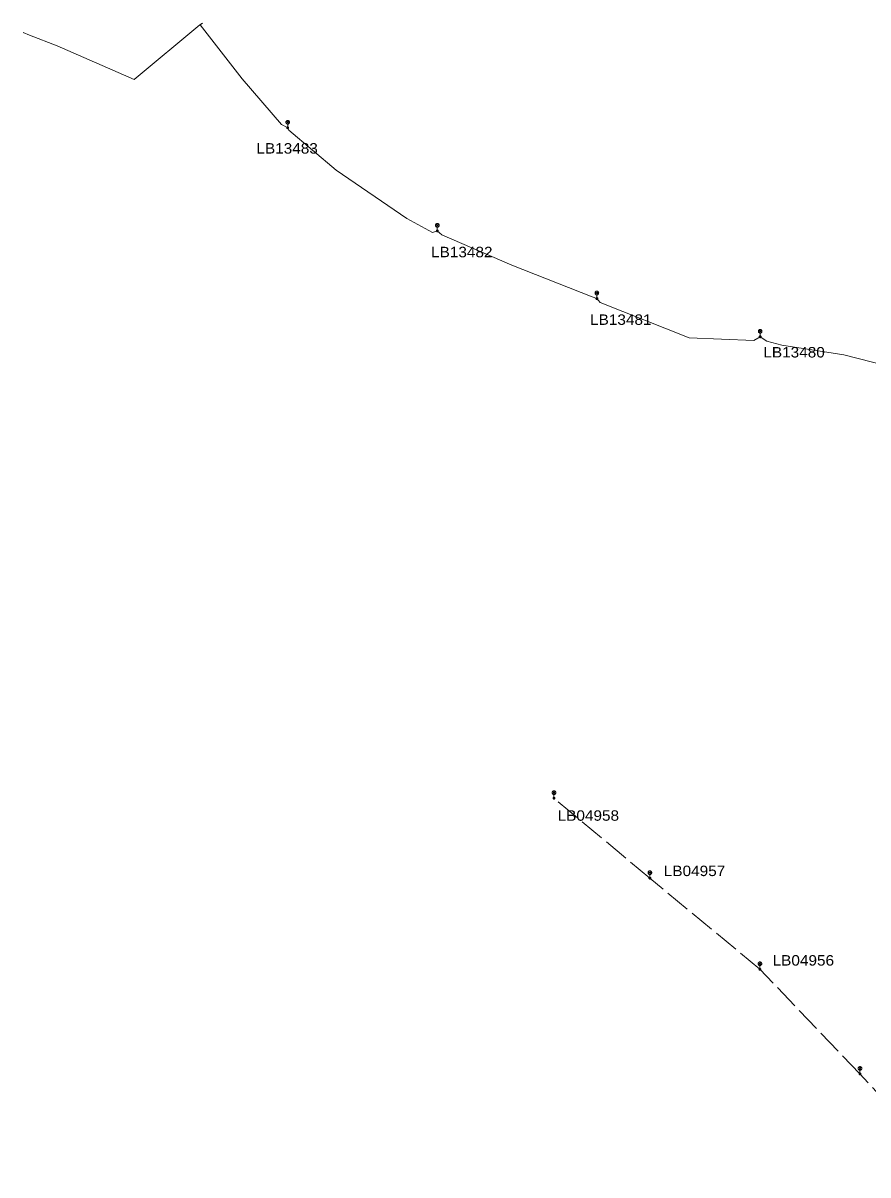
# Model space of a CAD drawing. Extents: x -690018 to -689415, y -972457 to -972107.
# Drawn here: x -690017.9 to -689842.5, y -972367.8 to -972128.6 of the extents above; entities that cross this region are included whole.
import ezdxf

# ---------------------------------------------------------------- set-up
doc = ezdxf.new("R2010")
doc.units = 0
doc.header["$LTSCALE"] = 0.87
doc.linetypes.add('LONG_DASHED', pattern=[7.5, 6, -1.5])
doc.layers.add('1', color=7, linetype='Continuous', lineweight=13)

msp = doc.modelspace()

# ---------------------------------------------------------------- linework, layer by layer
at = {"layer": '1'}
for p, q in [((-689963.195, -972148.955), (-689962.665, -972149.485)), ((-689963.195, -972149.485), (-689962.665, -972148.955)), ((-689962.93, -972150.37), (-689962.93, -972149.595)), ((-689932.135, -972170.365), (-689931.605, -972170.895)), ((-689932.135, -972170.895), (-689931.605, -972170.365)), ((-689931.87, -972171.78), (-689931.87, -972171.005)), ((-689899.005, -972184.415), (-689898.475, -972184.945)), ((-689899.005, -972184.945), (-689898.475, -972184.415)), ((-689898.74, -972185.83), (-689898.74, -972185.055)), ((-689865.095, -972192.355), (-689864.565, -972192.885)), ((-689865.095, -972192.885), (-689864.565, -972192.355)), ((-689864.83, -972193.77), (-689864.83, -972192.995)), ((-689907.912, -972288.185), (-689907.382, -972288.715)), ((-689907.912, -972288.715), (-689907.382, -972288.185)), ((-689907.647, -972289.6), (-689907.647, -972288.825)), ((-689887.998, -972304.793), (-689887.468, -972305.323)), ((-689887.998, -972305.323), (-689887.468, -972304.793)), ((-689887.733, -972306.208), (-689887.733, -972305.433)), ((-689865.155, -972323.71), (-689864.625, -972324.24)), ((-689865.155, -972324.24), (-689864.625, -972323.71)), ((-689864.89, -972325.125), (-689864.89, -972324.35)), ((-689844.376, -972345.444), (-689843.846, -972345.974)), ((-689844.376, -972345.974), (-689843.846, -972345.444)), ((-689844.111, -972346.859), (-689844.111, -972346.084))]:
    msp.add_line(p, q, dxfattribs=at)
at = {"layer": '1', "linetype": 'LONG_DASHED'}
for p, q in [((-689887.733, -972306.208), (-689907.647, -972289.6)), ((-689864.89, -972325.125), (-689887.733, -972306.208)), ((-689844.111, -972346.859), (-689864.89, -972325.125)), ((-689824.64, -972367.84), (-689844.111, -972346.859))]:
    msp.add_line(p, q, dxfattribs=at)
at = {"layer": '1'}
for points in [[(-689980.613, -972128.614), (-689981.155, -972128.982), (-689994.789, -972140.341), (-690010.821, -972133.353), (-690016.558, -972131.106), (-690017.89, -972130.601)], [(-689980.613, -972128.614), (-689981.081, -972129.019), (-689972.397, -972140.21), (-689964.203, -972149.703), (-689962.93, -972150.37)], [(-689962.93, -972150.37), (-689962.694, -972150.846), (-689952.88, -972159.16), (-689938.221, -972169.176), (-689932.88, -972172.102), (-689931.87, -972171.78)], [(-689931.87, -972171.78), (-689930.933, -972172.628), (-689916.423, -972178.917), (-689899.71, -972185.465), (-689898.74, -972185.83)], [(-689864.83, -972193.77), (-689866.149, -972194.545), (-689879.577, -972193.963), (-689898.079, -972186.654), (-689898.74, -972185.83)], [(-689831.69, -972201.27), (-689832.862, -972201.27), (-689847.448, -972197.511), (-689860.303, -972195.527), (-689863.452, -972194.661), (-689864.83, -972193.77)]]:
    msp.add_lwpolyline(points, dxfattribs=at)
for points in [[(-689962.555, -972149.22), (-689962.561, -972149.155), (-689962.578, -972149.092), (-689962.605, -972149.032), (-689962.643, -972148.979), (-689962.689, -972148.933), (-689962.742, -972148.895), (-689962.802, -972148.868), (-689962.865, -972148.851), (-689962.93, -972148.845), (-689962.995, -972148.851), (-689963.058, -972148.868), (-689963.118, -972148.895), (-689963.171, -972148.933), (-689963.217, -972148.979), (-689963.255, -972149.032), (-689963.282, -972149.092), (-689963.299, -972149.155), (-689963.305, -972149.22), (-689963.299, -972149.285), (-689963.282, -972149.348), (-689963.255, -972149.408), (-689963.217, -972149.461), (-689963.171, -972149.507), (-689963.118, -972149.545), (-689963.058, -972149.572), (-689962.995, -972149.589), (-689962.93, -972149.595), (-689962.865, -972149.589), (-689962.802, -972149.572), (-689962.742, -972149.545), (-689962.689, -972149.507), (-689962.643, -972149.461), (-689962.605, -972149.408), (-689962.578, -972149.348), (-689962.561, -972149.285)], [(-689962.74, -972150.37), (-689962.743, -972150.337), (-689962.751, -972150.305), (-689962.765, -972150.275), (-689962.784, -972150.248), (-689962.808, -972150.224), (-689962.835, -972150.205), (-689962.865, -972150.191), (-689962.897, -972150.183), (-689962.93, -972150.18), (-689962.963, -972150.183), (-689962.995, -972150.191), (-689963.025, -972150.205), (-689963.052, -972150.224), (-689963.076, -972150.248), (-689963.095, -972150.275), (-689963.109, -972150.305), (-689963.117, -972150.337), (-689963.12, -972150.37), (-689963.117, -972150.403), (-689963.109, -972150.435), (-689963.095, -972150.465), (-689963.076, -972150.492), (-689963.052, -972150.516), (-689963.025, -972150.535), (-689962.995, -972150.549), (-689962.963, -972150.557), (-689962.93, -972150.56), (-689962.897, -972150.557), (-689962.865, -972150.549), (-689962.835, -972150.535), (-689962.808, -972150.516), (-689962.784, -972150.492), (-689962.765, -972150.465), (-689962.751, -972150.435), (-689962.743, -972150.403)], [(-689962.88, -972150.37), (-689962.881, -972150.361), (-689962.883, -972150.353), (-689962.887, -972150.345), (-689962.892, -972150.338), (-689962.898, -972150.332), (-689962.905, -972150.327), (-689962.913, -972150.323), (-689962.921, -972150.321), (-689962.93, -972150.32), (-689962.939, -972150.321), (-689962.947, -972150.323), (-689962.955, -972150.327), (-689962.962, -972150.332), (-689962.968, -972150.338), (-689962.973, -972150.345), (-689962.977, -972150.353), (-689962.979, -972150.361), (-689962.98, -972150.37), (-689962.979, -972150.379), (-689962.977, -972150.387), (-689962.973, -972150.395), (-689962.968, -972150.402), (-689962.962, -972150.408), (-689962.955, -972150.413), (-689962.947, -972150.417), (-689962.939, -972150.419), (-689962.93, -972150.42), (-689962.921, -972150.419), (-689962.913, -972150.417), (-689962.905, -972150.413), (-689962.898, -972150.408), (-689962.892, -972150.402), (-689962.887, -972150.395), (-689962.883, -972150.387), (-689962.881, -972150.379)], [(-689931.495, -972170.63), (-689931.501, -972170.565), (-689931.518, -972170.502), (-689931.545, -972170.442), (-689931.583, -972170.389), (-689931.629, -972170.343), (-689931.682, -972170.305), (-689931.742, -972170.278), (-689931.805, -972170.261), (-689931.87, -972170.255), (-689931.935, -972170.261), (-689931.998, -972170.278), (-689932.058, -972170.305), (-689932.111, -972170.343), (-689932.157, -972170.389), (-689932.195, -972170.442), (-689932.222, -972170.502), (-689932.239, -972170.565), (-689932.245, -972170.63), (-689932.239, -972170.695), (-689932.222, -972170.758), (-689932.195, -972170.818), (-689932.157, -972170.871), (-689932.111, -972170.917), (-689932.058, -972170.955), (-689931.998, -972170.982), (-689931.935, -972170.999), (-689931.87, -972171.005), (-689931.805, -972170.999), (-689931.742, -972170.982), (-689931.682, -972170.955), (-689931.629, -972170.917), (-689931.583, -972170.871), (-689931.545, -972170.818), (-689931.518, -972170.758), (-689931.501, -972170.695)], [(-689931.68, -972171.78), (-689931.683, -972171.747), (-689931.691, -972171.715), (-689931.705, -972171.685), (-689931.724, -972171.658), (-689931.748, -972171.634), (-689931.775, -972171.615), (-689931.805, -972171.601), (-689931.837, -972171.593), (-689931.87, -972171.59), (-689931.903, -972171.593), (-689931.935, -972171.601), (-689931.965, -972171.615), (-689931.992, -972171.634), (-689932.016, -972171.658), (-689932.035, -972171.685), (-689932.049, -972171.715), (-689932.057, -972171.747), (-689932.06, -972171.78), (-689932.057, -972171.813), (-689932.049, -972171.845), (-689932.035, -972171.875), (-689932.016, -972171.902), (-689931.992, -972171.926), (-689931.965, -972171.945), (-689931.935, -972171.959), (-689931.903, -972171.967), (-689931.87, -972171.97), (-689931.837, -972171.967), (-689931.805, -972171.959), (-689931.775, -972171.945), (-689931.748, -972171.926), (-689931.724, -972171.902), (-689931.705, -972171.875), (-689931.691, -972171.845), (-689931.683, -972171.813)], [(-689931.82, -972171.78), (-689931.821, -972171.771), (-689931.823, -972171.763), (-689931.827, -972171.755), (-689931.832, -972171.748), (-689931.838, -972171.742), (-689931.845, -972171.737), (-689931.853, -972171.733), (-689931.861, -972171.731), (-689931.87, -972171.73), (-689931.879, -972171.731), (-689931.887, -972171.733), (-689931.895, -972171.737), (-689931.902, -972171.742), (-689931.908, -972171.748), (-689931.913, -972171.755), (-689931.917, -972171.763), (-689931.919, -972171.771), (-689931.92, -972171.78), (-689931.919, -972171.789), (-689931.917, -972171.797), (-689931.913, -972171.805), (-689931.908, -972171.812), (-689931.902, -972171.818), (-689931.895, -972171.823), (-689931.887, -972171.827), (-689931.879, -972171.829), (-689931.87, -972171.83), (-689931.861, -972171.829), (-689931.853, -972171.827), (-689931.845, -972171.823), (-689931.838, -972171.818), (-689931.832, -972171.812), (-689931.827, -972171.805), (-689931.823, -972171.797), (-689931.821, -972171.789)], [(-689898.365, -972184.68), (-689898.371, -972184.615), (-689898.388, -972184.552), (-689898.415, -972184.492), (-689898.453, -972184.439), (-689898.499, -972184.393), (-689898.552, -972184.355), (-689898.612, -972184.328), (-689898.675, -972184.311), (-689898.74, -972184.305), (-689898.805, -972184.311), (-689898.868, -972184.328), (-689898.928, -972184.355), (-689898.981, -972184.393), (-689899.027, -972184.439), (-689899.065, -972184.492), (-689899.092, -972184.552), (-689899.109, -972184.615), (-689899.115, -972184.68), (-689899.109, -972184.745), (-689899.092, -972184.808), (-689899.065, -972184.868), (-689899.027, -972184.921), (-689898.981, -972184.967), (-689898.928, -972185.005), (-689898.868, -972185.032), (-689898.805, -972185.049), (-689898.74, -972185.055), (-689898.675, -972185.049), (-689898.612, -972185.032), (-689898.552, -972185.005), (-689898.499, -972184.967), (-689898.453, -972184.921), (-689898.415, -972184.868), (-689898.388, -972184.808), (-689898.371, -972184.745)], [(-689898.55, -972185.83), (-689898.553, -972185.797), (-689898.561, -972185.765), (-689898.575, -972185.735), (-689898.594, -972185.708), (-689898.618, -972185.684), (-689898.645, -972185.665), (-689898.675, -972185.651), (-689898.707, -972185.643), (-689898.74, -972185.64), (-689898.773, -972185.643), (-689898.805, -972185.651), (-689898.835, -972185.665), (-689898.862, -972185.684), (-689898.886, -972185.708), (-689898.905, -972185.735), (-689898.919, -972185.765), (-689898.927, -972185.797), (-689898.93, -972185.83), (-689898.927, -972185.863), (-689898.919, -972185.895), (-689898.905, -972185.925), (-689898.886, -972185.952), (-689898.862, -972185.976), (-689898.835, -972185.995), (-689898.805, -972186.009), (-689898.773, -972186.017), (-689898.74, -972186.02), (-689898.707, -972186.017), (-689898.675, -972186.009), (-689898.645, -972185.995), (-689898.618, -972185.976), (-689898.594, -972185.952), (-689898.575, -972185.925), (-689898.561, -972185.895), (-689898.553, -972185.863)], [(-689898.69, -972185.83), (-689898.691, -972185.821), (-689898.693, -972185.813), (-689898.697, -972185.805), (-689898.702, -972185.798), (-689898.708, -972185.792), (-689898.715, -972185.787), (-689898.723, -972185.783), (-689898.731, -972185.781), (-689898.74, -972185.78), (-689898.749, -972185.781), (-689898.757, -972185.783), (-689898.765, -972185.787), (-689898.772, -972185.792), (-689898.778, -972185.798), (-689898.783, -972185.805), (-689898.787, -972185.813), (-689898.789, -972185.821), (-689898.79, -972185.83), (-689898.789, -972185.839), (-689898.787, -972185.847), (-689898.783, -972185.855), (-689898.778, -972185.862), (-689898.772, -972185.868), (-689898.765, -972185.873), (-689898.757, -972185.877), (-689898.749, -972185.879), (-689898.74, -972185.88), (-689898.731, -972185.879), (-689898.723, -972185.877), (-689898.715, -972185.873), (-689898.708, -972185.868), (-689898.702, -972185.862), (-689898.697, -972185.855), (-689898.693, -972185.847), (-689898.691, -972185.839)], [(-689864.455, -972192.62), (-689864.461, -972192.555), (-689864.478, -972192.492), (-689864.505, -972192.432), (-689864.543, -972192.379), (-689864.589, -972192.333), (-689864.642, -972192.295), (-689864.702, -972192.268), (-689864.765, -972192.251), (-689864.83, -972192.245), (-689864.895, -972192.251), (-689864.958, -972192.268), (-689865.018, -972192.295), (-689865.071, -972192.333), (-689865.117, -972192.379), (-689865.155, -972192.432), (-689865.182, -972192.492), (-689865.199, -972192.555), (-689865.205, -972192.62), (-689865.199, -972192.685), (-689865.182, -972192.748), (-689865.155, -972192.808), (-689865.117, -972192.861), (-689865.071, -972192.907), (-689865.018, -972192.945), (-689864.958, -972192.972), (-689864.895, -972192.989), (-689864.83, -972192.995), (-689864.765, -972192.989), (-689864.702, -972192.972), (-689864.642, -972192.945), (-689864.589, -972192.907), (-689864.543, -972192.861), (-689864.505, -972192.808), (-689864.478, -972192.748), (-689864.461, -972192.685)], [(-689864.64, -972193.77), (-689864.643, -972193.737), (-689864.651, -972193.705), (-689864.665, -972193.675), (-689864.684, -972193.648), (-689864.708, -972193.624), (-689864.735, -972193.605), (-689864.765, -972193.591), (-689864.797, -972193.583), (-689864.83, -972193.58), (-689864.863, -972193.583), (-689864.895, -972193.591), (-689864.925, -972193.605), (-689864.952, -972193.624), (-689864.976, -972193.648), (-689864.995, -972193.675), (-689865.009, -972193.705), (-689865.017, -972193.737), (-689865.02, -972193.77), (-689865.017, -972193.803), (-689865.009, -972193.835), (-689864.995, -972193.865), (-689864.976, -972193.892), (-689864.952, -972193.916), (-689864.925, -972193.935), (-689864.895, -972193.949), (-689864.863, -972193.957), (-689864.83, -972193.96), (-689864.797, -972193.957), (-689864.765, -972193.949), (-689864.735, -972193.935), (-689864.708, -972193.916), (-689864.684, -972193.892), (-689864.665, -972193.865), (-689864.651, -972193.835), (-689864.643, -972193.803)], [(-689864.78, -972193.77), (-689864.781, -972193.761), (-689864.783, -972193.753), (-689864.787, -972193.745), (-689864.792, -972193.738), (-689864.798, -972193.732), (-689864.805, -972193.727), (-689864.813, -972193.723), (-689864.821, -972193.721), (-689864.83, -972193.72), (-689864.839, -972193.721), (-689864.847, -972193.723), (-689864.855, -972193.727), (-689864.862, -972193.732), (-689864.868, -972193.738), (-689864.873, -972193.745), (-689864.877, -972193.753), (-689864.879, -972193.761), (-689864.88, -972193.77), (-689864.879, -972193.779), (-689864.877, -972193.787), (-689864.873, -972193.795), (-689864.868, -972193.802), (-689864.862, -972193.808), (-689864.855, -972193.813), (-689864.847, -972193.817), (-689864.839, -972193.819), (-689864.83, -972193.82), (-689864.821, -972193.819), (-689864.813, -972193.817), (-689864.805, -972193.813), (-689864.798, -972193.808), (-689864.792, -972193.802), (-689864.787, -972193.795), (-689864.783, -972193.787), (-689864.781, -972193.779)], [(-689907.272, -972288.45), (-689907.278, -972288.385), (-689907.295, -972288.321), (-689907.322, -972288.262), (-689907.36, -972288.209), (-689907.406, -972288.162), (-689907.459, -972288.125), (-689907.519, -972288.097), (-689907.582, -972288.08), (-689907.647, -972288.075), (-689907.712, -972288.08), (-689907.775, -972288.097), (-689907.834, -972288.125), (-689907.888, -972288.162), (-689907.934, -972288.209), (-689907.972, -972288.262), (-689907.999, -972288.321), (-689908.016, -972288.385), (-689908.022, -972288.45), (-689908.016, -972288.515), (-689907.999, -972288.578), (-689907.972, -972288.637), (-689907.934, -972288.691), (-689907.888, -972288.737), (-689907.834, -972288.774), (-689907.775, -972288.802), (-689907.712, -972288.819), (-689907.647, -972288.825), (-689907.582, -972288.819), (-689907.519, -972288.802), (-689907.459, -972288.774), (-689907.406, -972288.737), (-689907.36, -972288.691), (-689907.322, -972288.637), (-689907.295, -972288.578), (-689907.278, -972288.515)], [(-689907.457, -972289.6), (-689907.46, -972289.567), (-689907.468, -972289.535), (-689907.482, -972289.505), (-689907.501, -972289.478), (-689907.525, -972289.454), (-689907.552, -972289.435), (-689907.582, -972289.421), (-689907.614, -972289.413), (-689907.647, -972289.41), (-689907.68, -972289.413), (-689907.712, -972289.421), (-689907.742, -972289.435), (-689907.769, -972289.454), (-689907.792, -972289.478), (-689907.811, -972289.505), (-689907.825, -972289.535), (-689907.834, -972289.567), (-689907.837, -972289.6), (-689907.834, -972289.633), (-689907.825, -972289.665), (-689907.811, -972289.695), (-689907.792, -972289.722), (-689907.769, -972289.745), (-689907.742, -972289.764), (-689907.712, -972289.778), (-689907.68, -972289.787), (-689907.647, -972289.79), (-689907.614, -972289.787), (-689907.582, -972289.778), (-689907.552, -972289.764), (-689907.525, -972289.745), (-689907.501, -972289.722), (-689907.482, -972289.695), (-689907.468, -972289.665), (-689907.46, -972289.633)], [(-689907.597, -972289.6), (-689907.598, -972289.591), (-689907.6, -972289.583), (-689907.604, -972289.575), (-689907.609, -972289.568), (-689907.615, -972289.561), (-689907.622, -972289.556), (-689907.63, -972289.553), (-689907.638, -972289.55), (-689907.647, -972289.55), (-689907.656, -972289.55), (-689907.664, -972289.553), (-689907.672, -972289.556), (-689907.679, -972289.561), (-689907.685, -972289.568), (-689907.69, -972289.575), (-689907.694, -972289.583), (-689907.696, -972289.591), (-689907.697, -972289.6), (-689907.696, -972289.608), (-689907.694, -972289.617), (-689907.69, -972289.625), (-689907.685, -972289.632), (-689907.679, -972289.638), (-689907.672, -972289.643), (-689907.664, -972289.647), (-689907.656, -972289.649), (-689907.647, -972289.65), (-689907.638, -972289.649), (-689907.63, -972289.647), (-689907.622, -972289.643), (-689907.615, -972289.638), (-689907.609, -972289.632), (-689907.604, -972289.625), (-689907.6, -972289.617), (-689907.598, -972289.608)], [(-689887.358, -972305.058), (-689887.363, -972304.993), (-689887.38, -972304.93), (-689887.408, -972304.871), (-689887.446, -972304.817), (-689887.492, -972304.771), (-689887.545, -972304.733), (-689887.605, -972304.706), (-689887.668, -972304.689), (-689887.733, -972304.683), (-689887.798, -972304.689), (-689887.861, -972304.706), (-689887.92, -972304.733), (-689887.974, -972304.771), (-689888.02, -972304.817), (-689888.058, -972304.871), (-689888.085, -972304.93), (-689888.102, -972304.993), (-689888.108, -972305.058), (-689888.102, -972305.123), (-689888.085, -972305.186), (-689888.058, -972305.246), (-689888.02, -972305.299), (-689887.974, -972305.345), (-689887.92, -972305.383), (-689887.861, -972305.41), (-689887.798, -972305.427), (-689887.733, -972305.433), (-689887.668, -972305.427), (-689887.605, -972305.41), (-689887.545, -972305.383), (-689887.492, -972305.345), (-689887.446, -972305.299), (-689887.408, -972305.246), (-689887.38, -972305.186), (-689887.363, -972305.123)], [(-689887.543, -972306.208), (-689887.546, -972306.175), (-689887.554, -972306.143), (-689887.568, -972306.113), (-689887.587, -972306.086), (-689887.611, -972306.062), (-689887.638, -972306.044), (-689887.668, -972306.03), (-689887.7, -972306.021), (-689887.733, -972306.018), (-689887.766, -972306.021), (-689887.798, -972306.03), (-689887.828, -972306.044), (-689887.855, -972306.062), (-689887.878, -972306.086), (-689887.897, -972306.113), (-689887.911, -972306.143), (-689887.92, -972306.175), (-689887.923, -972306.208), (-689887.92, -972306.241), (-689887.911, -972306.273), (-689887.897, -972306.303), (-689887.878, -972306.33), (-689887.855, -972306.354), (-689887.828, -972306.373), (-689887.798, -972306.387), (-689887.766, -972306.395), (-689887.733, -972306.398), (-689887.7, -972306.395), (-689887.668, -972306.387), (-689887.638, -972306.373), (-689887.611, -972306.354), (-689887.587, -972306.33), (-689887.568, -972306.303), (-689887.554, -972306.273), (-689887.546, -972306.241)], [(-689887.683, -972306.208), (-689887.684, -972306.199), (-689887.686, -972306.191), (-689887.689, -972306.183), (-689887.694, -972306.176), (-689887.701, -972306.17), (-689887.708, -972306.165), (-689887.716, -972306.161), (-689887.724, -972306.159), (-689887.733, -972306.158), (-689887.741, -972306.159), (-689887.75, -972306.161), (-689887.758, -972306.165), (-689887.765, -972306.17), (-689887.771, -972306.176), (-689887.776, -972306.183), (-689887.78, -972306.191), (-689887.782, -972306.199), (-689887.783, -972306.208), (-689887.782, -972306.217), (-689887.78, -972306.225), (-689887.776, -972306.233), (-689887.771, -972306.24), (-689887.765, -972306.246), (-689887.758, -972306.251), (-689887.75, -972306.255), (-689887.741, -972306.257), (-689887.733, -972306.258), (-689887.724, -972306.257), (-689887.716, -972306.255), (-689887.708, -972306.251), (-689887.701, -972306.246), (-689887.694, -972306.24), (-689887.689, -972306.233), (-689887.686, -972306.225), (-689887.684, -972306.217)], [(-689864.515, -972323.975), (-689864.521, -972323.91), (-689864.538, -972323.847), (-689864.565, -972323.788), (-689864.603, -972323.734), (-689864.649, -972323.688), (-689864.702, -972323.65), (-689864.762, -972323.623), (-689864.825, -972323.606), (-689864.89, -972323.6), (-689864.955, -972323.606), (-689865.018, -972323.623), (-689865.078, -972323.65), (-689865.131, -972323.688), (-689865.177, -972323.734), (-689865.215, -972323.788), (-689865.242, -972323.847), (-689865.259, -972323.91), (-689865.265, -972323.975), (-689865.259, -972324.04), (-689865.242, -972324.103), (-689865.215, -972324.162), (-689865.177, -972324.216), (-689865.131, -972324.262), (-689865.078, -972324.3), (-689865.018, -972324.327), (-689864.955, -972324.344), (-689864.89, -972324.35), (-689864.825, -972324.344), (-689864.762, -972324.327), (-689864.702, -972324.3), (-689864.649, -972324.262), (-689864.603, -972324.216), (-689864.565, -972324.162), (-689864.538, -972324.103), (-689864.521, -972324.04)], [(-689864.7, -972325.125), (-689864.703, -972325.092), (-689864.711, -972325.06), (-689864.725, -972325.03), (-689864.744, -972325.003), (-689864.768, -972324.979), (-689864.795, -972324.96), (-689864.825, -972324.946), (-689864.857, -972324.938), (-689864.89, -972324.935), (-689864.923, -972324.938), (-689864.955, -972324.946), (-689864.985, -972324.96), (-689865.012, -972324.979), (-689865.036, -972325.003), (-689865.055, -972325.03), (-689865.069, -972325.06), (-689865.077, -972325.092), (-689865.08, -972325.125), (-689865.077, -972325.158), (-689865.069, -972325.19), (-689865.055, -972325.22), (-689865.036, -972325.247), (-689865.012, -972325.271), (-689864.985, -972325.29), (-689864.955, -972325.304), (-689864.923, -972325.312), (-689864.89, -972325.315), (-689864.857, -972325.312), (-689864.825, -972325.304), (-689864.795, -972325.29), (-689864.768, -972325.271), (-689864.744, -972325.247), (-689864.725, -972325.22), (-689864.711, -972325.19), (-689864.703, -972325.158)], [(-689864.84, -972325.125), (-689864.841, -972325.116), (-689864.843, -972325.108), (-689864.847, -972325.1), (-689864.852, -972325.093), (-689864.858, -972325.087), (-689864.865, -972325.082), (-689864.873, -972325.078), (-689864.881, -972325.076), (-689864.89, -972325.075), (-689864.899, -972325.076), (-689864.907, -972325.078), (-689864.915, -972325.082), (-689864.922, -972325.087), (-689864.928, -972325.093), (-689864.933, -972325.1), (-689864.937, -972325.108), (-689864.939, -972325.116), (-689864.94, -972325.125), (-689864.939, -972325.134), (-689864.937, -972325.142), (-689864.933, -972325.15), (-689864.928, -972325.157), (-689864.922, -972325.163), (-689864.915, -972325.168), (-689864.907, -972325.172), (-689864.899, -972325.174), (-689864.89, -972325.175), (-689864.881, -972325.174), (-689864.873, -972325.172), (-689864.865, -972325.168), (-689864.858, -972325.163), (-689864.852, -972325.157), (-689864.847, -972325.15), (-689864.843, -972325.142), (-689864.841, -972325.134)], [(-689843.736, -972345.709), (-689843.742, -972345.644), (-689843.759, -972345.581), (-689843.787, -972345.521), (-689843.824, -972345.468), (-689843.87, -972345.422), (-689843.924, -972345.384), (-689843.983, -972345.357), (-689844.046, -972345.34), (-689844.111, -972345.334), (-689844.177, -972345.34), (-689844.24, -972345.357), (-689844.299, -972345.384), (-689844.352, -972345.422), (-689844.399, -972345.468), (-689844.436, -972345.521), (-689844.464, -972345.581), (-689844.481, -972345.644), (-689844.486, -972345.709), (-689844.481, -972345.774), (-689844.464, -972345.837), (-689844.436, -972345.896), (-689844.399, -972345.95), (-689844.352, -972345.996), (-689844.299, -972346.034), (-689844.24, -972346.061), (-689844.177, -972346.078), (-689844.111, -972346.084), (-689844.046, -972346.078), (-689843.983, -972346.061), (-689843.924, -972346.034), (-689843.87, -972345.996), (-689843.824, -972345.95), (-689843.787, -972345.896), (-689843.759, -972345.837), (-689843.742, -972345.774)], [(-689843.921, -972346.859), (-689843.924, -972346.826), (-689843.933, -972346.794), (-689843.947, -972346.764), (-689843.966, -972346.737), (-689843.989, -972346.713), (-689844.016, -972346.694), (-689844.046, -972346.68), (-689844.078, -972346.672), (-689844.111, -972346.669), (-689844.144, -972346.672), (-689844.176, -972346.68), (-689844.206, -972346.694), (-689844.234, -972346.713), (-689844.257, -972346.737), (-689844.276, -972346.764), (-689844.29, -972346.794), (-689844.299, -972346.826), (-689844.301, -972346.859), (-689844.299, -972346.892), (-689844.29, -972346.924), (-689844.276, -972346.954), (-689844.257, -972346.981), (-689844.234, -972347.005), (-689844.206, -972347.024), (-689844.176, -972347.038), (-689844.144, -972347.046), (-689844.111, -972347.049), (-689844.078, -972347.046), (-689844.046, -972347.038), (-689844.016, -972347.024), (-689843.989, -972347.005), (-689843.966, -972346.981), (-689843.947, -972346.954), (-689843.933, -972346.924), (-689843.924, -972346.892)], [(-689844.061, -972346.859), (-689844.062, -972346.85), (-689844.064, -972346.842), (-689844.068, -972346.834), (-689844.073, -972346.827), (-689844.079, -972346.821), (-689844.086, -972346.816), (-689844.094, -972346.812), (-689844.103, -972346.81), (-689844.111, -972346.809), (-689844.12, -972346.81), (-689844.129, -972346.812), (-689844.136, -972346.816), (-689844.144, -972346.821), (-689844.15, -972346.827), (-689844.155, -972346.834), (-689844.158, -972346.842), (-689844.161, -972346.85), (-689844.161, -972346.859), (-689844.161, -972346.868), (-689844.158, -972346.876), (-689844.155, -972346.884), (-689844.15, -972346.891), (-689844.144, -972346.897), (-689844.136, -972346.902), (-689844.129, -972346.906), (-689844.12, -972346.908), (-689844.111, -972346.909), (-689844.103, -972346.908), (-689844.094, -972346.906), (-689844.086, -972346.902), (-689844.079, -972346.897), (-689844.073, -972346.891), (-689844.068, -972346.884), (-689844.064, -972346.876), (-689844.062, -972346.868)]]:
    msp.add_lwpolyline(points, close=True, dxfattribs=at)

# ---------------------------------------------------------------- texts
at = {"layer": '1', "width": 1.1}
for s, p in [('LB13483', (-689969.438, -972155.723)), ('LB13482', (-689933.175, -972177.254)), ('LB13481', (-689900.157, -972191.294)), ('LB13480', (-689864.177, -972198.071)), ('LB04958', (-689906.897, -972294.278)), ('LB04957', (-689884.845, -972305.77)), ('LB04956', (-689862.254, -972324.355))]:
    msp.add_text(s, height=2.167, dxfattribs=at).set_placement(p)

doc.saveas('drawing.dxf')
